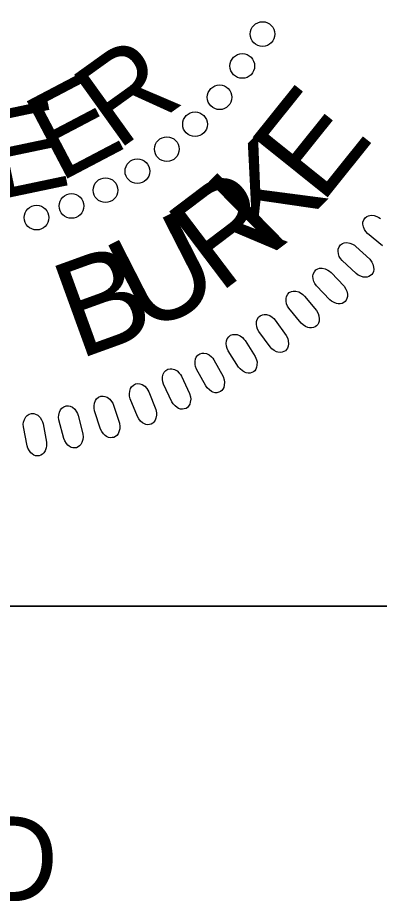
# Model space of a CAD drawing. Extents: x 497599 to 513368, y 404140 to 476034.
# Drawn here: x 507314.2 to 507337.7, y 439679.4 to 439736.8 of the extents above; entities that cross this region are included whole.
import ezdxf

# ---------------------------------------------------------------- set-up
doc = ezdxf.new("R2010")
doc.units = 0
for name, color, linetype in [('Sheet PE Seal Cell', 7, 'Continuous'), ('Sheet Profile CELL', 7, 'Continuous'), ('Sheet Sticker Exception Certification CELL', 7, 'Continuous')]:
    doc.layers.add(name, color=color, linetype=linetype)

msp = doc.modelspace()

# ---------------------------------------------------------------- linework, layer by layer
at = {"layer": 'Sheet PE Seal Cell'}
msp.add_lwpolyline([(507337.911, 439722.001), (507336.938, 439722.797), (507336.822, 439722.922), (507336.743, 439723.046), (507336.678, 439723.216), (507336.641, 439723.392), (507336.642, 439723.518), (507336.696, 439723.677), (507336.777, 439723.805), (507336.902, 439723.894), (507337.007, 439723.943), (507337.165, 439723.978), (507337.372, 439723.962), (507337.553, 439723.899), (507337.672, 439723.839), (507337.781, 439723.768)], dxfattribs=at)
for points in [[(507336.187, 439721.957), (507337.081, 439721.117), (507337.216, 439720.94), (507337.281, 439720.806), (507337.328, 439720.608), (507337.341, 439720.462), (507337.323, 439720.325), (507337.28, 439720.222), (507337.217, 439720.127), (507337.127, 439720.059), (507337.022, 439719.992), (507336.908, 439719.956), (507336.763, 439719.949), (507336.664, 439719.96), (507336.509, 439720.013), (507336.337, 439720.092), (507336.205, 439720.185), (507335.285, 439721.04), (507335.177, 439721.173), (507335.106, 439721.302), (507335.051, 439721.476), (507335.026, 439721.653), (507335.034, 439721.779), (507335.097, 439721.934), (507335.186, 439722.057), (507335.318, 439722.138), (507335.426, 439722.18), (507335.585, 439722.205), (507335.79, 439722.175), (507335.968, 439722.102), (507336.083, 439722.035)], [(507334.575, 439720.263), (507335.415, 439719.369), (507335.537, 439719.183), (507335.595, 439719.045), (507335.629, 439718.845), (507335.633, 439718.698), (507335.606, 439718.563), (507335.557, 439718.463), (507335.489, 439718.371), (507335.393, 439718.31), (507335.286, 439718.25), (507335.169, 439718.221), (507335.024, 439718.223), (507334.926, 439718.24), (507334.775, 439718.303), (507334.608, 439718.393), (507334.483, 439718.494), (507333.617, 439719.405), (507333.517, 439719.544), (507333.455, 439719.677), (507333.411, 439719.854), (507333.397, 439720.032), (507333.414, 439720.157), (507333.487, 439720.309), (507333.582, 439720.425), (507333.718, 439720.498), (507333.829, 439720.533), (507333.99, 439720.548), (507334.193, 439720.507), (507334.365, 439720.421), (507334.475, 439720.348)], [(507332.842, 439718.734), (507333.624, 439717.788), (507333.735, 439717.595), (507333.784, 439717.455), (507333.806, 439717.252), (507333.801, 439717.106), (507333.765, 439716.973), (507333.71, 439716.876), (507333.636, 439716.789), (507333.537, 439716.733), (507333.425, 439716.68), (507333.307, 439716.659), (507333.163, 439716.669), (507333.066, 439716.692), (507332.918, 439716.765), (507332.758, 439716.866), (507332.639, 439716.974), (507331.833, 439717.937), (507331.742, 439718.083), (507331.688, 439718.219), (507331.655, 439718.399), (507331.652, 439718.578), (507331.677, 439718.701), (507331.759, 439718.847), (507331.862, 439718.958), (507332.002, 439719.022), (507332.115, 439719.051), (507332.277, 439719.055), (507332.476, 439719.001), (507332.643, 439718.905), (507332.749, 439718.824)], [(507330.936, 439717.168), (507331.656, 439716.175), (507331.755, 439715.976), (507331.796, 439715.833), (507331.804, 439715.63), (507331.79, 439715.483), (507331.746, 439715.352), (507331.685, 439715.259), (507331.605, 439715.177), (507331.504, 439715.128), (507331.389, 439715.082), (507331.27, 439715.068), (507331.126, 439715.088), (507331.03, 439715.117), (507330.888, 439715.199), (507330.734, 439715.309), (507330.622, 439715.424), (507329.878, 439716.437), (507329.797, 439716.587), (507329.752, 439716.727), (507329.73, 439716.908), (507329.738, 439717.087), (507329.77, 439717.209), (507329.862, 439717.35), (507329.972, 439717.454), (507330.116, 439717.509), (507330.23, 439717.53), (507330.391, 439717.524), (507330.587, 439717.458), (507330.748, 439717.352), (507330.848, 439717.264)], [(507328.992, 439715.84), (507329.649, 439714.804), (507329.735, 439714.599), (507329.766, 439714.453), (507329.762, 439714.249), (507329.739, 439714.104), (507329.687, 439713.977), (507329.62, 439713.887), (507329.535, 439713.81), (507329.43, 439713.768), (507329.313, 439713.728), (507329.193, 439713.723), (507329.051, 439713.751), (507328.958, 439713.786), (507328.821, 439713.877), (507328.674, 439713.996), (507328.57, 439714.119), (507327.891, 439715.176), (507327.819, 439715.331), (507327.782, 439715.473), (507327.772, 439715.656), (507327.792, 439715.834), (507327.832, 439715.953), (507327.932, 439716.088), (507328.048, 439716.185), (507328.195, 439716.232), (507328.31, 439716.245), (507328.471, 439716.23), (507328.663, 439716.15), (507328.816, 439716.034), (507328.91, 439715.941)], [(507326.973, 439714.584), (507327.564, 439713.508), (507327.637, 439713.298), (507327.658, 439713.151), (507327.642, 439712.948), (507327.609, 439712.805), (507327.549, 439712.681), (507327.477, 439712.596), (507327.388, 439712.524), (507327.281, 439712.488), (507327.161, 439712.457), (507327.041, 439712.458), (507326.901, 439712.496), (507326.81, 439712.537), (507326.679, 439712.636), (507326.54, 439712.764), (507326.444, 439712.893), (507325.832, 439713.991), (507325.77, 439714.15), (507325.743, 439714.295), (507325.744, 439714.477), (507325.775, 439714.653), (507325.822, 439714.771), (507325.931, 439714.899), (507326.052, 439714.988), (507326.202, 439715.025), (507326.318, 439715.032), (507326.478, 439715.006), (507326.664, 439714.914), (507326.81, 439714.789), (507326.898, 439714.69)], [(507324.871, 439713.52), (507325.393, 439712.41), (507325.453, 439712.196), (507325.465, 439712.047), (507325.436, 439711.846), (507325.395, 439711.705), (507325.327, 439711.585), (507325.249, 439711.505), (507325.156, 439711.439), (507325.047, 439711.41), (507324.925, 439711.386), (507324.805, 439711.395), (507324.668, 439711.441), (507324.58, 439711.487), (507324.456, 439711.594), (507324.325, 439711.731), (507324.237, 439711.866), (507323.696, 439713), (507323.643, 439713.163), (507323.625, 439713.309), (507323.638, 439713.491), (507323.68, 439713.665), (507323.734, 439713.779), (507323.851, 439713.9), (507323.978, 439713.981), (507324.13, 439714.009), (507324.246, 439714.008), (507324.403, 439713.973), (507324.583, 439713.87), (507324.721, 439713.735), (507324.803, 439713.631)], [(507322.744, 439712.513), (507323.195, 439711.372), (507323.24, 439711.154), (507323.244, 439711.006), (507323.202, 439710.806), (507323.152, 439710.669), (507323.077, 439710.553), (507322.994, 439710.478), (507322.897, 439710.418), (507322.786, 439710.396), (507322.663, 439710.379), (507322.544, 439710.396), (507322.41, 439710.451), (507322.325, 439710.503), (507322.207, 439710.617), (507322.086, 439710.762), (507322.006, 439710.902), (507321.537, 439712.068), (507321.496, 439712.234), (507321.486, 439712.38), (507321.511, 439712.562), (507321.563, 439712.732), (507321.625, 439712.843), (507321.748, 439712.956), (507321.881, 439713.03), (507322.034, 439713.048), (507322.15, 439713.039), (507322.304, 439712.994), (507322.477, 439712.88), (507322.607, 439712.738), (507322.682, 439712.628)], [(507320.452, 439711.654), (507320.83, 439710.487), (507320.862, 439710.268), (507320.856, 439710.118), (507320.802, 439709.922), (507320.743, 439709.788), (507320.661, 439709.677), (507320.574, 439709.607), (507320.472, 439709.554), (507320.36, 439709.538), (507320.237, 439709.53), (507320.119, 439709.554), (507319.989, 439709.617), (507319.907, 439709.674), (507319.797, 439709.796), (507319.685, 439709.948), (507319.614, 439710.093), (507319.219, 439711.286), (507319.189, 439711.454), (507319.188, 439711.601), (507319.224, 439711.78), (507319.287, 439711.947), (507319.356, 439712.053), (507319.486, 439712.159), (507319.622, 439712.224), (507319.776, 439712.232), (507319.892, 439712.216), (507320.043, 439712.162), (507320.209, 439712.037), (507320.329, 439711.887), (507320.398, 439711.773)], [(507318.159, 439710.983), (507318.464, 439709.794), (507318.482, 439709.573), (507318.467, 439709.424), (507318.4, 439709.232), (507318.333, 439709.102), (507318.244, 439708.997), (507318.153, 439708.932), (507318.049, 439708.885), (507317.936, 439708.877), (507317.813, 439708.876), (507317.696, 439708.907), (507317.57, 439708.978), (507317.493, 439709.041), (507317.39, 439709.169), (507317.288, 439709.328), (507317.226, 439709.477), (507316.907, 439710.692), (507316.886, 439710.862), (507316.895, 439711.008), (507316.943, 439711.186), (507317.016, 439711.348), (507317.091, 439711.45), (507317.228, 439711.547), (507317.368, 439711.603), (507317.523, 439711.601), (507317.637, 439711.579), (507317.784, 439711.515), (507317.942, 439711.38), (507318.052, 439711.222), (507318.113, 439711.105)], [(507315.874, 439710.445), (507316.103, 439709.239), (507316.108, 439709.017), (507316.083, 439708.87), (507316.004, 439708.683), (507315.929, 439708.557), (507315.834, 439708.457), (507315.739, 439708.398), (507315.631, 439708.358), (507315.518, 439708.357), (507315.395, 439708.364), (507315.281, 439708.403), (507315.16, 439708.481), (507315.086, 439708.548), (507314.992, 439708.683), (507314.899, 439708.848), (507314.847, 439709.001), (507314.605, 439710.234), (507314.595, 439710.404), (507314.614, 439710.55), (507314.672, 439710.723), (507314.755, 439710.881), (507314.836, 439710.978), (507314.979, 439711.066), (507315.123, 439711.114), (507315.276, 439711.102), (507315.389, 439711.073), (507315.533, 439710.999), (507315.681, 439710.855), (507315.782, 439710.69), (507315.835, 439710.569)]]:
    msp.add_lwpolyline(points, close=True, dxfattribs=at)
for centre in [(507330.124, 439735.74), (507328.809, 439733.669), (507327.335, 439731.638), (507325.742, 439729.886), (507323.913, 439728.27), (507322.002, 439726.836), (507319.931, 439725.602), (507317.724, 439724.58), (507315.455, 439723.823)]:
    msp.add_circle(centre, 0.801, dxfattribs=at)
at = {"layer": 'Sheet Profile CELL'}
msp.add_lwpolyline([(507258.678, 439811.094), (507358.678, 439811.094), (507358.678, 439698.594), (507258.678, 439698.594)], close=True, dxfattribs=at)
at = {"layer": 'Sheet Sticker Exception Certification CELL'}
msp.add_line((507158.628, 439698.594), (507358.665, 439698.594), dxfattribs=at)
msp.add_line((507158.628, 439698.594), (507358.665, 439698.594), dxfattribs=at)

# ---------------------------------------------------------------- texts
at = {"layer": 'Sheet PE Seal Cell'}
for s, height, rotation, p in [('R', 5.669, 35.66356, (507320.691, 439728.133)), ('E', 5.669, 27.72376, (507316.911, 439726.071)), ('E', 6.236, 51.26826, (507333.921, 439724.607)), ('E', 5.669, 11.84417, (507312.84, 439724.948)), ('K', 6.236, 44.4226, (507330.515, 439721.233)), ('R', 6.236, 37.14757, (507327.284, 439718.841)), ('U', 6.236, 27.04772, (507322.38, 439716.173)), ('B', 6.236, 19.93088, (507318.161, 439714.592))]:
    msp.add_text(s, height=height, rotation=rotation, dxfattribs=at).set_placement(p)
at = {"layer": 'Sheet Sticker Exception Certification CELL'}
msp.add_text('UNLESS ALL SIGNATURES COMPLETED', height=5.5, dxfattribs=at).set_placement((507174.627, 439679.449))
msp.add_text('UNLESS ALL SIGNATURES COMPLETED', height=5.5, dxfattribs=at).set_placement((507174.627, 439679.449))

doc.saveas('drawing.dxf')
